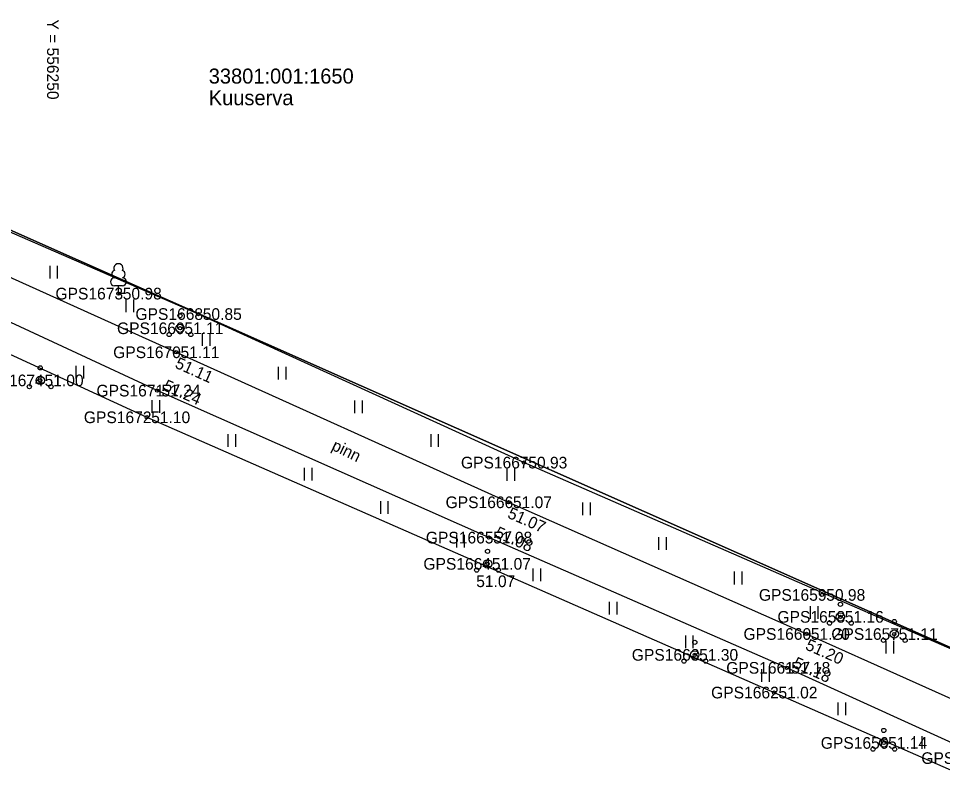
# Model space of a CAD drawing. Extents: x 551623 to 559850, y 6561220 to 6567135.
# Drawn here: x 556248 to 556303.4, y 6565252.6 to 6565297.9 of the extents above; entities that cross this region are included whole.
import ezdxf

# ---------------------------------------------------------------- set-up
doc = ezdxf.new("R2010")
doc.units = 0
for name, color, linetype in [('HALJASTUS', 7, 'Continuous'), ('KORGUS-EH2000', 7, 'Continuous'), ('MOOTKORG-EH2000', 7, 'Continuous'), ('MOOTMPUNKT', 7, 'Continuous'), ('MOOTNR', 7, 'Continuous'), ('MOOTPIIR', 7, 'Continuous'), ('PIIR', 7, 'Continuous'), ('PUU', 7, 'Continuous'), ('TEE', 7, 'Continuous'), ('VORK', 7, 'Continuous')]:
    doc.layers.add(name, color=color, linetype=linetype)

msp = doc.modelspace()

# ---------------------------------------------------------------- linework, layer by layer
at = {"layer": 'HALJASTUS'}
for p, q in [((556249.843, 6565283.084), (556249.843, 6565282.323)), ((556250.299, 6565283.084), (556250.299, 6565282.323)), ((556254.416, 6565281.06), (556254.416, 6565280.299)), ((556254.871, 6565281.06), (556254.871, 6565280.299)), ((556258.988, 6565279.037), (556258.988, 6565278.275)), ((556259.443, 6565279.037), (556259.443, 6565278.275)), ((556251.418, 6565277.078), (556251.418, 6565276.317)), ((556251.873, 6565277.078), (556251.873, 6565276.317)), ((556263.56, 6565277.013), (556263.56, 6565276.252)), ((556264.015, 6565277.013), (556264.015, 6565276.252)), ((556255.973, 6565275.016), (556255.973, 6565274.255)), ((556256.428, 6565275.016), (556256.428, 6565274.255)), ((556268.132, 6565274.989), (556268.132, 6565274.228)), ((556268.587, 6565274.989), (556268.587, 6565274.228)), ((556260.533, 6565272.965), (556260.533, 6565272.204)), ((556260.988, 6565272.965), (556260.988, 6565272.204)), ((556272.704, 6565272.965), (556272.704, 6565272.204)), ((556273.159, 6565272.965), (556273.159, 6565272.204)), ((556265.109, 6565270.951), (556265.109, 6565270.19)), ((556265.564, 6565270.951), (556265.564, 6565270.19)), ((556277.273, 6565270.935), (556277.273, 6565270.174)), ((556277.728, 6565270.935), (556277.728, 6565270.174)), ((556269.686, 6565268.937), (556269.686, 6565268.176)), ((556270.141, 6565268.937), (556270.141, 6565268.176)), ((556281.823, 6565268.861), (556281.823, 6565268.1)), ((556282.278, 6565268.861), (556282.278, 6565268.1)), ((556274.262, 6565266.923), (556274.262, 6565266.162)), ((556274.717, 6565266.923), (556274.717, 6565266.162)), ((556286.373, 6565266.788), (556286.373, 6565266.027)), ((556286.828, 6565266.788), (556286.828, 6565266.027)), ((556278.838, 6565264.908), (556278.838, 6565264.147)), ((556279.293, 6565264.908), (556279.293, 6565264.147)), ((556290.923, 6565264.714), (556290.923, 6565263.953)), ((556291.378, 6565264.714), (556291.378, 6565263.953)), ((556283.415, 6565262.894), (556283.415, 6565262.133)), ((556283.87, 6565262.894), (556283.87, 6565262.133)), ((556295.472, 6565262.641), (556295.472, 6565261.88)), ((556295.928, 6565262.641), (556295.928, 6565261.88)), ((556287.991, 6565260.88), (556287.991, 6565260.119)), ((556288.446, 6565260.88), (556288.446, 6565260.119)), ((556300.022, 6565260.567), (556300.022, 6565259.806)), ((556300.477, 6565260.567), (556300.477, 6565259.806)), ((556292.567, 6565258.866), (556292.567, 6565258.105)), ((556293.022, 6565258.866), (556293.022, 6565258.105)), ((556297.144, 6565256.852), (556297.144, 6565256.091)), ((556297.599, 6565256.852), (556297.599, 6565256.091)), ((556301.719, 6565254.836), (556301.719, 6565254.075)), ((556302.174, 6565254.836), (556302.174, 6565254.075))]:
    msp.add_line(p, q, dxfattribs=at)
at = {"layer": 'KORGUS-EH2000'}
for centre in [(556258.766, 6565280.179), (556257.431, 6565277.885), (556256.289, 6565275.582), (556255.671, 6565273.981), (556278.301, 6565271.261), (556277.379, 6565268.878), (556276.195, 6565266.757), (556276.117, 6565265.183), (556296.181, 6565263.316), (556295.258, 6565260.972), (556294.082, 6565258.94), (556293.314, 6565257.455), (556299.895, 6565254.432)]:
    msp.add_circle(centre, 0.1, dxfattribs=at)
at = {"layer": 'MOOTMPUNKT'}
for centre in [(556253.966, 6565281.405), (556258.766, 6565280.179), (556257.661, 6565279.325), (556257.431, 6565277.885), (556249.273, 6565276.196), (556256.289, 6565275.582), (556255.671, 6565273.981), (556278.301, 6565271.261), (556277.379, 6565268.878), (556276.195, 6565266.757), (556276.117, 6565265.183), (556296.181, 6565263.316), (556297.293, 6565262.001), (556295.258, 6565260.972), (556300.527, 6565260.97), (556288.554, 6565259.719), (556294.082, 6565258.94), (556293.314, 6565257.455), (556299.895, 6565254.432)]:
    msp.add_circle(centre, 0.1, dxfattribs=at)
at = {"layer": 'MOOTPIIR'}
for points in [[(556319.439, 6565253.295), (556278.301, 6565271.261), (556258.766, 6565280.179), (556222.735, 6565295.867), (556225.084, 6565299.935), (556245.706, 6565305.674), (556269.066, 6565311.081), (556283.768, 6565312.214), (556299.17, 6565314.853), (556317.928, 6565317.026)], [(556193.422, 6565244.254), (556204.14, 6565266.613), (556211.176, 6565280.356), (556216.206, 6565287.008), (556218.339, 6565289.743), (556230.388, 6565285.614), (556255.671, 6565273.981), (556293.314, 6565257.455), (556317.811, 6565246.714)]]:
    msp.add_lwpolyline(points, dxfattribs=at)
at = {"layer": 'PIIR'}
for points in [[(556217.39, 6565298.59), (556213.87, 6565303.19), (556229.81, 6565311.25), (556335.44, 6565331.24), (556350.73, 6565342.07), (556507.54, 6565334), (556519.21, 6565368.05), (556548.5, 6565368.1), (556612.15, 6565380.04), (556615.14, 6565380.2), (556613.56, 6565366.23), (556611.32, 6565356.67), (556591.74, 6565273.2), (556570.09, 6565180.67), (556561.87, 6565145.74), (556557.67, 6565147.61), (556393.49, 6565220.36)], [(556206.35, 6565280.04), (556217.39, 6565298.59), (556393.49, 6565220.36), (556274.8, 6564990.28), (556228.34, 6565008.72), (556105.05, 6565057.69), (556140.52, 6565135.89), (556229.38, 6565104.35), (556274.08, 6565194.99), (556184.08, 6565232.1), (556196.52, 6565258.88), (556203.12, 6565272.11)]]:
    msp.add_lwpolyline(points, close=True, dxfattribs=at)
at = {"layer": 'PUU'}
for p, q in [((556254.206, 6565281.88), (556253.726, 6565281.88)), ((556253.966, 6565281.405), (556253.966, 6565281.88)), ((556254.346, 6565281.405), (556253.966, 6565281.405))]:
    msp.add_line(p, q, dxfattribs=at)
for centre, radius in [((556257.661, 6565280.075), 0.125), ((556257.661, 6565279.325), 0.25), ((556257.011, 6565278.95), 0.125), ((556258.311, 6565278.95), 0.125), ((556249.273, 6565276.946), 0.125), ((556249.273, 6565276.196), 0.25), ((556248.623, 6565275.821), 0.125), ((556249.923, 6565275.821), 0.125), ((556276.117, 6565265.933), 0.125), ((556276.117, 6565265.183), 0.25), ((556275.467, 6565264.808), 0.125), ((556276.767, 6565264.808), 0.125), ((556297.293, 6565262.751), 0.125), ((556297.293, 6565262.001), 0.25), ((556296.643, 6565261.626), 0.125), ((556297.943, 6565261.626), 0.125), ((556300.527, 6565261.72), 0.125), ((556300.527, 6565260.97), 0.25), ((556288.554, 6565260.469), 0.125), ((556299.877, 6565260.595), 0.125), ((556301.177, 6565260.595), 0.125), ((556288.554, 6565259.719), 0.25), ((556287.904, 6565259.344), 0.125), ((556289.204, 6565259.344), 0.125), ((556299.895, 6565255.182), 0.125), ((556299.895, 6565254.432), 0.25), ((556299.245, 6565254.057), 0.125), ((556300.545, 6565254.057), 0.125)]:
    msp.add_circle(centre, radius, dxfattribs=at)
for centre, radius, start, end in [((556253.966, 6565282.925), 0.277, 332.5799, 207.4201), ((556253.796, 6565282.577), 0.233, 109.0217, 253.1415), ((556254.136, 6565282.577), 0.233, 286.8508, 70.9859), ((556253.729, 6565282.117), 0.238, 90.0016, 269.3953), ((556254.203, 6565282.117), 0.238, 270.6047, 89.9984)]:
    msp.add_arc(centre, radius, start, end, dxfattribs=at)
at = {"layer": 'TEE'}
for points in [[(556212.519, 6565297.656), (556233.204, 6565288.814), (556257.431, 6565277.885), (556277.379, 6565268.878), (556295.258, 6565260.972), (556307.223, 6565255.623), (556319.32, 6565250.223), (556331.627, 6565244.871), (556340.735, 6565240.974), (556360.587, 6565232.345), (556381.381, 6565222.917), (556405.852, 6565212.41), (556418.096, 6565207.028), (556442.438, 6565196.365)], [(556563.777, 6565138.667), (556560.868, 6565140.849), (556553.174, 6565143.6), (556545.589, 6565147.013), (556535.182, 6565151.57), (556522.842, 6565156.959), (556502.184, 6565166.778), (556486.192, 6565174.091), (556471.011, 6565180.892), (556450.062, 6565190.454), (556440.995, 6565194.267), (556416.948, 6565204.811), (556405, 6565210.263), (556380.262, 6565220.954), (556359.747, 6565229.991), (556339.784, 6565238.7), (556330.661, 6565242.666), (556318.495, 6565248.069), (556305.998, 6565253.52), (556294.082, 6565258.94), (556276.195, 6565266.757), (556256.289, 6565275.582), (556232.166, 6565286.787), (556209.59, 6565295.964)]]:
    msp.add_lwpolyline(points, dxfattribs=at)

# ---------------------------------------------------------------- texts
at = {"layer": 'KORGUS-EH2000'}
for s, p in [(' 50.85', (556258.766, 6565279.829)), (' 51.10', (556255.671, 6565273.631)), (' 50.93', (556278.301, 6565270.911)), (' 51.07', (556275.177, 6565263.788)), (' 50.98', (556296.181, 6565262.967)), (' 51.02', (556293.314, 6565257.105)), (' 51.14', (556299.895, 6565254.082))]:
    msp.add_text(s, height=0.7, dxfattribs=at).set_placement(p)
for s, rotation, p in [(' 51.11', 335.6986, (556257.071, 6565277.088)), (' 51.24', 336.0891, (556256.36, 6565275.742)), (' 51.07', 336.146, (556277.025, 6565268.077)), (' 51.08', 336.3942, (556276.265, 6565266.917)), (' 51.20', 335.9144, (556294.901, 6565260.173)), (' 51.18', 335.5435, (556294.155, 6565259.099))]:
    msp.add_text(s, height=0.7, rotation=rotation, dxfattribs=at).set_placement(p)
at = {"layer": 'MOOTKORG-EH2000'}
for s, p in [(' 50.98', (556253.966, 6565281.055)), (' 50.85', (556258.766, 6565279.829)), (' 51.11', (556257.661, 6565278.975)), (' 51.11', (556257.431, 6565277.535)), (' 51.00', (556249.273, 6565275.846)), (' 51.24', (556256.289, 6565275.232)), (' 51.10', (556255.671, 6565273.631)), (' 50.93', (556278.301, 6565270.911)), (' 51.07', (556277.379, 6565268.528)), (' 51.08', (556276.195, 6565266.407)), (' 51.07', (556276.117, 6565264.833)), (' 50.98', (556296.181, 6565262.967)), (' 51.16', (556297.293, 6565261.651)), (' 51.20', (556295.258, 6565260.622)), (' 51.11', (556300.527, 6565260.62)), (' 51.30', (556288.554, 6565259.369)), (' 51.18', (556294.082, 6565258.59)), (' 51.02', (556293.314, 6565257.105)), (' 51.14', (556299.895, 6565254.082))]:
    msp.add_text(s, height=0.7, dxfattribs=at).set_placement(p)
at = {"layer": 'MOOTNR'}
for s, p in [('GPS1673 ', (556250.186, 6565281.055)), ('GPS1668 ', (556254.986, 6565279.829)), ('GPS1669 ', (556253.881, 6565278.975)), ('GPS1670 ', (556253.651, 6565277.535)), ('GPS1674 ', (556245.423, 6565275.846)), ('GPS1671 ', (556252.649, 6565275.232)), ('GPS1672 ', (556251.891, 6565273.631)), ('GPS1667 ', (556274.521, 6565270.911)), ('GPS1666 ', (556273.6, 6565268.528)), ('GPS1665 ', (556272.415, 6565266.407)), ('GPS1664 ', (556272.267, 6565264.833)), ('GPS1659 ', (556292.401, 6565262.967)), ('GPS1658 ', (556293.514, 6565261.651)), ('GPS1660 ', (556291.478, 6565260.622)), ('GPS1657 ', (556296.747, 6565260.62)), ('GPS1663 ', (556284.774, 6565259.369)), ('GPS1661 ', (556290.442, 6565258.59)), ('GPS1662 ', (556289.534, 6565257.105)), ('GPS1656 ', (556296.116, 6565254.082)), ('GPS1654 ', (556302.149, 6565253.17))]:
    msp.add_text(s, height=0.7, dxfattribs=at).set_placement(p)
at = {"layer": 'PIIR'}
for s, p in [('33801:001:1650', (556259.385, 6565294.016)), ('Kuuserva', (556259.385, 6565292.716))]:
    msp.add_text(s, height=0.9, dxfattribs=at).set_placement(p)
at = {"layer": 'TEE'}
msp.add_text('pinn', height=0.7, rotation=333.8614, dxfattribs=at).set_placement((556266.707, 6565272.056))
at = {"layer": 'VORK'}
msp.add_text('Y = 556250 ', height=0.7, rotation=270, dxfattribs=at).set_placement((556249.683, 6565297.871))

doc.saveas('drawing.dxf')
